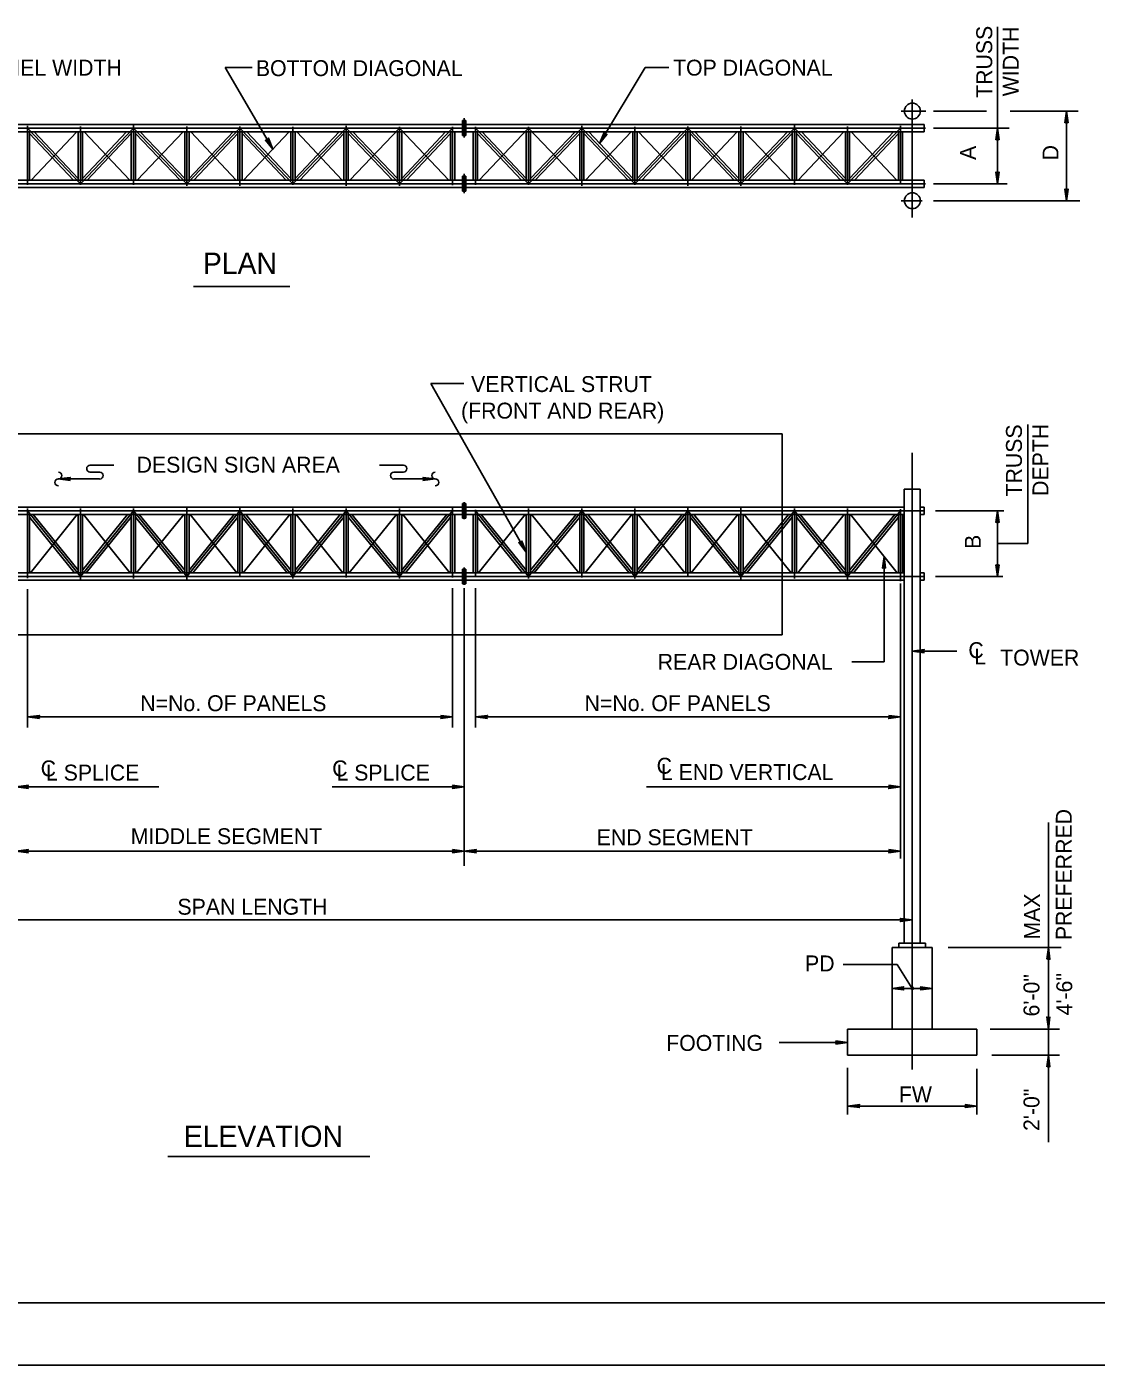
# Model space of a CAD drawing. Extents: x -3 to 26050223, y 0 to 12035012.
# Drawn here: x 14.2 to 31.01, y 0 to 21.04 of the extents above; entities that cross this region are included whole.
import ezdxf

# ---------------------------------------------------------------- set-up
doc = ezdxf.new("R2010")
doc.units = 0
for name, color, linetype in [('1', 7, 'Continuous'), ('2', 7, 'Continuous'), ('39', 7, 'Continuous')]:
    doc.layers.add(name, color=color, linetype=linetype)

msp = doc.modelspace()

# ---------------------------------------------------------------- linework, layer by layer
at = {"layer": '1'}
for p, q in [((29.458, 21.042), (29.458, 19.45)), ((17.317, 20.4), (18.067, 19.117)), ((17.317, 20.4), (17.742, 20.4)), ((23.2, 19.208), (23.917, 20.4)), ((23.917, 20.4), (24.292, 20.4)), ((28.117, 19.9), (28.117, 18.042)), ((21.075, 19.608), (21.075, 19.3)), ((21.075, 19.583), (21.075, 19.308)), ((27.942, 19.717), (28.333, 19.717)), ((28.45, 19.717), (29.283, 19.717)), ((29.658, 19.717), (30.725, 19.717)), ((30.542, 19.717), (30.542, 18.308)), ((6.792, 19.508), (28.308, 19.508)), ((6.792, 19.45), (28.325, 19.45)), ((6.792, 19.392), (28.308, 19.392)), ((14.208, 19.483), (14.208, 18.558)), ((15.042, 18.575), (14.208, 19.45)), ((14.242, 19.392), (14.242, 18.633)), ((14.242, 19.392), (14.242, 18.633)), ((14.933, 18.633), (14.242, 19.367)), ((14.983, 19.392), (14.267, 18.633)), ((15.008, 18.658), (14.317, 19.392)), ((15.008, 19.392), (15.008, 18.633)), ((15.042, 19.475), (15.042, 18.558)), ((15.875, 19.45), (15.042, 18.575)), ((15.767, 19.392), (15.075, 18.658)), ((15.075, 19.392), (15.075, 18.633)), ((15.817, 18.633), (15.1, 19.392)), ((15.842, 19.367), (15.15, 18.633)), ((15.842, 19.392), (15.842, 18.633)), ((15.875, 19.492), (15.875, 18.558)), ((16.717, 18.575), (15.875, 19.45)), ((15.908, 19.392), (15.908, 18.633)), ((16.608, 18.633), (15.908, 19.367)), ((16.658, 19.392), (15.933, 18.633)), ((16.683, 18.658), (15.983, 19.392)), ((16.683, 19.392), (16.683, 18.633)), ((16.717, 19.475), (16.717, 18.542)), ((17.55, 19.45), (16.717, 18.575)), ((17.442, 19.392), (16.75, 18.658)), ((16.75, 19.392), (16.75, 18.633)), ((17.492, 18.633), (16.775, 19.392)), ((17.517, 19.367), (16.825, 18.633)), ((17.517, 19.392), (17.517, 18.633)), ((17.55, 19.475), (17.55, 18.542)), ((18.383, 18.575), (17.55, 19.45)), ((17.583, 19.392), (17.583, 18.633)), ((18.275, 18.633), (17.583, 19.367)), ((18.325, 19.392), (17.608, 18.633)), ((18.35, 18.658), (17.658, 19.392)), ((18.35, 19.392), (18.35, 18.633)), ((18.383, 19.467), (18.383, 18.558)), ((19.217, 19.45), (18.383, 18.575)), ((19.108, 19.392), (18.417, 18.658)), ((18.417, 19.392), (18.417, 18.633)), ((19.158, 18.633), (18.442, 19.392)), ((19.183, 19.367), (18.492, 18.633)), ((19.183, 19.392), (19.183, 18.633)), ((19.217, 19.483), (19.217, 18.542)), ((20.058, 18.575), (19.217, 19.45)), ((19.25, 19.392), (19.25, 18.633)), ((19.95, 18.633), (19.25, 19.367)), ((20.058, 19.45), (19.275, 18.633)), ((20.025, 18.658), (19.325, 19.392)), ((20.025, 19.392), (20.025, 18.633)), ((20.058, 19.467), (20.058, 18.542)), ((20.892, 19.45), (20.058, 18.575)), ((20.833, 18.633), (20.058, 19.45)), ((20.783, 19.392), (20.092, 18.658)), ((20.092, 19.392), (20.092, 18.633)), ((20.858, 19.367), (20.167, 18.633)), ((20.858, 19.392), (20.858, 18.633)), ((20.892, 19.467), (20.892, 18.55)), ((20.925, 19.392), (20.925, 18.633)), ((21.05, 19.567), (21.05, 19.333)), ((21.05, 19.567), (21.1, 19.567)), ((21.1, 19.567), (21.1, 19.333)), ((21.217, 19.392), (21.217, 18.633)), ((21.25, 19.467), (21.25, 18.558)), ((21.25, 19.45), (22.083, 18.575)), ((21.283, 19.392), (21.283, 18.633)), ((21.283, 19.367), (21.975, 18.633)), ((21.308, 18.633), (22.083, 19.45)), ((21.358, 19.392), (22.05, 18.658)), ((22.05, 19.392), (22.05, 18.633)), ((22.083, 19.467), (22.083, 18.558)), ((22.083, 18.575), (22.925, 19.45)), ((22.083, 19.45), (22.867, 18.633)), ((22.117, 18.658), (22.817, 19.392)), ((22.117, 19.392), (22.117, 18.633)), ((22.192, 18.633), (22.892, 19.367)), ((22.892, 19.392), (22.892, 18.633)), ((22.925, 19.483), (22.925, 18.542)), ((22.925, 19.45), (23.758, 18.575)), ((22.958, 19.392), (22.958, 18.633)), ((22.958, 19.367), (23.65, 18.633)), ((22.983, 18.633), (23.7, 19.392)), ((23.033, 19.392), (23.725, 18.658)), ((23.725, 19.392), (23.725, 18.633)), ((23.758, 19.467), (23.758, 18.558)), ((23.758, 18.575), (24.592, 19.45)), ((23.792, 18.658), (24.483, 19.392)), ((23.792, 19.392), (23.792, 18.633)), ((23.817, 19.392), (24.533, 18.633)), ((23.867, 18.633), (24.558, 19.367)), ((24.558, 19.392), (24.558, 18.633)), ((24.592, 19.475), (24.592, 18.542)), ((24.592, 19.45), (25.425, 18.575)), ((24.625, 19.392), (24.625, 18.633)), ((24.625, 19.367), (25.317, 18.633)), ((24.65, 18.633), (25.367, 19.392)), ((24.7, 19.392), (25.392, 18.658)), ((25.392, 19.392), (25.392, 18.633)), ((25.425, 19.475), (25.425, 18.542)), ((25.425, 18.575), (26.267, 19.45)), ((25.458, 18.658), (26.158, 19.392)), ((25.458, 19.392), (25.458, 18.633)), ((25.483, 19.392), (26.208, 18.633)), ((25.533, 18.633), (26.233, 19.367)), ((26.233, 19.392), (26.233, 18.633)), ((26.267, 19.492), (26.267, 18.558)), ((26.267, 19.45), (27.1, 18.575)), ((26.3, 19.392), (26.3, 18.633)), ((26.3, 19.367), (26.992, 18.633)), ((26.325, 18.633), (27.042, 19.392)), ((26.375, 19.392), (27.067, 18.658)), ((27.067, 19.392), (27.067, 18.633)), ((27.1, 19.475), (27.1, 18.558)), ((27.1, 18.575), (27.933, 19.45)), ((27.133, 18.658), (27.825, 19.392)), ((27.133, 19.392), (27.133, 18.633)), ((27.158, 19.392), (27.875, 18.633)), ((27.208, 18.633), (27.9, 19.367)), ((27.9, 19.392), (27.9, 18.633)), ((27.933, 19.483), (27.933, 18.567)), ((27.967, 19.392), (27.967, 18.633)), ((28.308, 19.508), (28.308, 19.392)), ((28.45, 19.45), (29.642, 19.45)), ((29.458, 19.45), (29.458, 18.575)), ((21.05, 19.333), (21.1, 19.333)), ((21.075, 18.733), (21.075, 18.425)), ((6.792, 18.633), (28.308, 18.633)), ((6.792, 18.575), (28.325, 18.575)), ((21.05, 18.692), (21.05, 18.458)), ((21.05, 18.692), (21.1, 18.692)), ((21.075, 18.708), (21.075, 18.442)), ((21.1, 18.692), (21.1, 18.458)), ((28.308, 18.633), (28.308, 18.517)), ((28.45, 18.575), (29.608, 18.575)), ((6.792, 18.517), (28.308, 18.517)), ((21.05, 18.458), (21.1, 18.458)), ((27.942, 18.308), (28.275, 18.308)), ((28.45, 18.308), (30.75, 18.308)), ((20.55, 15.433), (21.067, 15.433)), ((22.05, 12.783), (20.55, 15.433)), ((29.933, 14.792), (29.933, 12.917)), ((9.108, 14.642), (26.075, 14.642)), ((26.075, 14.642), (26.075, 11.483)), ((28.117, 14.342), (28.117, 4.65)), ((15.192, 14.15), (15.567, 14.15)), ((20.117, 14.15), (19.742, 14.15)), ((14.692, 13.933), (15.342, 13.933)), ((15.192, 14.042), (15.342, 14.042)), ((20.117, 14.042), (19.967, 14.042)), ((20.617, 13.933), (19.967, 13.933)), ((27.992, 13.775), (28.242, 13.775)), ((27.992, 13.775), (27.992, 6.633)), ((28.242, 13.775), (28.242, 6.633)), ((7.108, 13.492), (27.992, 13.492)), ((16.717, 13.475), (16.717, 12.358)), ((17.55, 13.475), (17.55, 12.392)), ((20.892, 13.475), (20.892, 12.383)), ((21.05, 13.55), (21.05, 13.317)), ((21.05, 13.55), (21.1, 13.55)), ((21.075, 13.567), (21.075, 13.3)), ((21.1, 13.55), (21.1, 13.317)), ((24.592, 13.475), (24.592, 12.392)), ((25.425, 13.475), (25.425, 12.358)), ((28.242, 13.492), (28.308, 13.492)), ((28.242, 13.492), (28.308, 13.492)), ((28.308, 13.492), (28.308, 13.375)), ((6.675, 13.433), (28.308, 13.433)), ((7.108, 13.375), (27.992, 13.375)), ((14.208, 13.467), (14.208, 12.375)), ((15.042, 12.4), (14.208, 13.433)), ((14.242, 13.375), (14.242, 12.458)), ((14.95, 12.458), (14.242, 13.333)), ((14.992, 13.375), (14.258, 12.458)), ((15.008, 12.5), (14.3, 13.375)), ((15.008, 13.375), (15.008, 12.458)), ((15.042, 13.467), (15.042, 12.358)), ((15.875, 13.433), (15.042, 12.4)), ((15.075, 13.375), (15.075, 12.458)), ((15.783, 13.375), (15.075, 12.5)), ((15.825, 12.458), (15.092, 13.375)), ((15.842, 13.333), (15.133, 12.458)), ((15.842, 13.375), (15.842, 12.458)), ((15.875, 13.467), (15.875, 12.367)), ((16.717, 12.4), (15.875, 13.433)), ((15.908, 13.375), (15.908, 12.458)), ((16.625, 12.458), (15.908, 13.333)), ((16.667, 13.375), (15.925, 12.458)), ((16.683, 12.5), (15.967, 13.375)), ((16.683, 13.375), (16.683, 12.458)), ((17.55, 13.433), (16.717, 12.4)), ((16.75, 13.375), (16.75, 12.458)), ((17.458, 13.375), (16.75, 12.5)), ((17.5, 12.458), (16.767, 13.375)), ((17.517, 13.333), (16.808, 12.458)), ((17.517, 13.375), (17.517, 12.458)), ((18.383, 12.4), (17.55, 13.433)), ((17.583, 13.375), (17.583, 12.458)), ((18.292, 12.458), (17.583, 13.333)), ((18.333, 13.375), (17.6, 12.458)), ((18.35, 12.5), (17.642, 13.375)), ((18.35, 13.375), (18.35, 12.458)), ((18.383, 13.467), (18.383, 12.367)), ((19.217, 13.433), (18.383, 12.4)), ((18.417, 13.375), (18.417, 12.458)), ((19.125, 13.375), (18.417, 12.5)), ((19.167, 12.458), (18.433, 13.375)), ((19.183, 13.333), (18.475, 12.458)), ((19.183, 13.375), (19.183, 12.458)), ((19.217, 13.467), (19.217, 12.383)), ((20.058, 12.4), (19.217, 13.433)), ((19.25, 13.375), (19.25, 12.458)), ((19.967, 12.458), (19.25, 13.333)), ((20.008, 13.375), (19.267, 12.458)), ((20.025, 12.5), (19.308, 13.375)), ((20.025, 13.375), (20.025, 12.458)), ((20.058, 13.467), (20.058, 12.367)), ((20.892, 13.433), (20.058, 12.4)), ((20.092, 13.375), (20.092, 12.458)), ((20.8, 13.375), (20.092, 12.5)), ((20.842, 12.458), (20.108, 13.375)), ((20.858, 13.333), (20.15, 12.458)), ((20.858, 13.375), (20.858, 12.458)), ((20.925, 13.375), (20.925, 12.458)), ((21.05, 13.317), (21.1, 13.317)), ((21.217, 13.375), (21.217, 12.458)), ((21.25, 13.45), (21.25, 12.392)), ((21.25, 13.433), (22.083, 12.4)), ((21.283, 13.375), (21.283, 12.458)), ((21.283, 13.333), (21.992, 12.458)), ((21.3, 12.458), (22.033, 13.375)), ((21.342, 13.375), (22.05, 12.5)), ((22.05, 13.375), (22.05, 12.458)), ((22.083, 13.467), (22.083, 12.367)), ((22.083, 12.4), (22.925, 13.433)), ((22.117, 13.375), (22.117, 12.458)), ((22.117, 12.5), (22.833, 13.375)), ((22.133, 13.375), (22.875, 12.458)), ((22.175, 12.458), (22.892, 13.333)), ((22.892, 13.375), (22.892, 12.458)), ((22.925, 13.467), (22.925, 12.383)), ((22.925, 13.433), (23.758, 12.4)), ((22.958, 13.375), (22.958, 12.458)), ((22.958, 13.333), (23.667, 12.458)), ((22.975, 12.458), (23.708, 13.375)), ((23.017, 13.375), (23.725, 12.5)), ((23.725, 13.375), (23.725, 12.458)), ((23.758, 13.467), (23.758, 12.367)), ((23.758, 12.4), (24.592, 13.433)), ((23.792, 13.375), (23.792, 12.458)), ((23.792, 12.5), (24.5, 13.375)), ((23.808, 13.375), (24.542, 12.458)), ((23.85, 12.458), (24.558, 13.333)), ((24.558, 13.375), (24.558, 12.458)), ((24.592, 13.433), (25.425, 12.4)), ((24.625, 13.375), (24.625, 12.458)), ((24.625, 13.333), (25.333, 12.458)), ((24.642, 12.458), (25.375, 13.375)), ((24.683, 13.375), (25.392, 12.5)), ((25.392, 13.375), (25.392, 12.458)), ((25.425, 12.4), (26.267, 13.433)), ((25.458, 13.375), (25.458, 12.458)), ((25.458, 12.5), (26.175, 13.375)), ((25.475, 13.375), (26.217, 12.458)), ((25.517, 12.458), (26.233, 13.333)), ((26.233, 13.375), (26.233, 12.458)), ((26.267, 13.467), (26.267, 12.367)), ((26.267, 13.433), (27.1, 12.4)), ((26.3, 13.375), (26.3, 12.458)), ((26.3, 13.333), (27.008, 12.458)), ((26.317, 12.458), (27.05, 13.375)), ((26.358, 13.375), (27.067, 12.5)), ((27.067, 13.375), (27.067, 12.458)), ((27.1, 13.467), (27.1, 12.358)), ((27.1, 12.4), (27.933, 13.433)), ((27.133, 12.5), (27.842, 13.375)), ((27.133, 13.375), (27.133, 12.458)), ((27.15, 13.375), (27.883, 12.458)), ((27.192, 12.458), (27.9, 13.333)), ((27.9, 13.375), (27.9, 12.458)), ((27.933, 13.458), (27.933, 12.325)), ((27.967, 13.375), (27.967, 12.458)), ((28.242, 13.375), (28.308, 13.375)), ((28.242, 13.375), (28.308, 13.375)), ((28.483, 13.433), (29.558, 13.433)), ((29.458, 13.433), (29.458, 12.4)), ((29.933, 12.917), (29.458, 12.917)), ((27.675, 11.058), (27.675, 12.717)), ((7.108, 12.458), (27.992, 12.458)), ((21.05, 12.517), (21.05, 12.283)), ((21.05, 12.517), (21.1, 12.517)), ((21.075, 12.542), (21.075, 12.267)), ((21.1, 12.517), (21.1, 12.283)), ((28.242, 12.458), (28.308, 12.458)), ((28.308, 12.458), (28.308, 12.342)), ((6.7, 12.4), (28.3, 12.4)), ((7.108, 12.342), (27.992, 12.342)), ((20.892, 12.217), (20.892, 10.025)), ((21.05, 12.283), (21.1, 12.283)), ((21.075, 12.217), (21.075, 7.85)), ((21.25, 12.217), (21.25, 10.025)), ((28.242, 12.342), (28.308, 12.342)), ((28.483, 12.4), (29.542, 12.4)), ((14.208, 12.2), (14.208, 10.025)), ((9.108, 11.483), (26.075, 11.483)), ((28.117, 11.225), (28.817, 11.225)), ((27.167, 11.058), (27.675, 11.058)), ((14.208, 10.192), (20.892, 10.192)), ((21.25, 10.192), (27.933, 10.192)), ((14.033, 9.092), (16.275, 9.092)), ((19, 9.092), (21.075, 9.092)), ((23.942, 9.092), (27.933, 9.092)), ((30.258, 8.533), (30.258, 6.567)), ((6.983, 7), (28.117, 7)), ((27.8, 6.567), (28.433, 6.567)), ((27.8, 6.567), (27.8, 5.283)), ((27.908, 6.633), (27.908, 6.567)), ((27.908, 6.633), (28.325, 6.633)), ((28.325, 6.633), (28.325, 6.567)), ((28.433, 6.567), (28.433, 5.283)), ((28.683, 6.567), (30.458, 6.567)), ((30.258, 6.567), (30.258, 5.283)), ((27.033, 6.3), (27.883, 6.3)), ((27.883, 6.3), (28.117, 5.925)), ((27.8, 5.925), (28.433, 5.925)), ((27.1, 5.283), (27.1, 4.875)), ((27.1, 5.283), (29.133, 5.283)), ((29.133, 5.283), (29.133, 4.875)), ((29.342, 5.283), (30.433, 5.283)), ((30.258, 5.283), (30.258, 4.875)), ((26.025, 5.075), (27.1, 5.075)), ((27.1, 4.875), (29.133, 4.875)), ((29.367, 4.875), (30.433, 4.875)), ((30.258, 4.875), (30.258, 3.508)), ((27.1, 4.675), (27.1, 3.942)), ((29.133, 4.658), (29.133, 3.942)), ((27.1, 4.075), (29.133, 4.075)), ((3.6, 0.983), (68.183, 0.983)), ((68.892, 0), (0, 0))]:
    msp.add_line(p, q, dxfattribs=at)
for points in [[(30.542, 19.55), (30.517, 19.533), (30.542, 19.717), (30.567, 19.533)], [(23.283, 19.35), (23.317, 19.35), (23.2, 19.208), (23.275, 19.383)], [(29.458, 19.283), (29.433, 19.267), (29.458, 19.45), (29.483, 19.267)], [(17.983, 19.258), (18, 19.292), (18.067, 19.117), (17.95, 19.258)], [(29.458, 18.742), (29.483, 18.758), (29.458, 18.575), (29.433, 18.758)], [(30.542, 18.475), (30.567, 18.492), (30.542, 18.308), (30.517, 18.492)], [(14.883, 13.908), (14.692, 13.933), (14.883, 13.958), (14.858, 13.933)], [(20.425, 13.908), (20.617, 13.933), (20.425, 13.958), (20.45, 13.933)], [(21.967, 12.933), (21.983, 12.958), (22.05, 12.783), (21.933, 12.933)], [(28.308, 11.2), (28.117, 11.225), (28.308, 11.25), (28.283, 11.225)], [(14.4, 10.167), (14.208, 10.192), (14.4, 10.217), (14.375, 10.192)], [(20.708, 10.217), (20.892, 10.192), (20.708, 10.167), (20.725, 10.192)], [(21.442, 10.167), (21.25, 10.192), (21.442, 10.217), (21.417, 10.192)], [(27.75, 10.217), (27.933, 10.192), (27.75, 10.167), (27.767, 10.192)], [(14.225, 9.067), (14.033, 9.092), (14.225, 9.117), (14.2, 9.092)], [(20.892, 9.117), (21.075, 9.092), (20.892, 9.067), (20.908, 9.092)], [(27.75, 9.117), (27.933, 9.092), (27.75, 9.067), (27.767, 9.092)], [(14.225, 8.058), (14.033, 8.083), (14.225, 8.108), (14.2, 8.083)], [(20.892, 8.108), (21.075, 8.083), (20.892, 8.058), (20.908, 8.083)], [(21.267, 8.058), (21.075, 8.083), (21.267, 8.108), (21.242, 8.083)], [(27.75, 8.108), (27.933, 8.083), (27.75, 8.058), (27.767, 8.083)], [(30.233, 6.383), (30.258, 6.567), (30.283, 6.383), (30.258, 6.4)], [(27.967, 5.925), (27.983, 5.9), (27.8, 5.925), (27.983, 5.95)], [(28.267, 5.925), (28.25, 5.95), (28.433, 5.925), (28.25, 5.9)], [(30.283, 5.475), (30.258, 5.283), (30.233, 5.475), (30.258, 5.45)], [(26.933, 5.075), (26.917, 5.1), (27.1, 5.075), (26.917, 5.05)], [(30.233, 4.692), (30.258, 4.875), (30.283, 4.692), (30.258, 4.708)], [(27.292, 4.05), (27.1, 4.075), (27.292, 4.1), (27.267, 4.075)], [(28.95, 4.1), (29.133, 4.075), (28.95, 4.05), (28.967, 4.075)]]:
    msp.add_lwpolyline(points, close=True, dxfattribs=at)
for centre, radius in [((28.12, 19.717), 0.125), ((28.12, 18.308), 0.125), ((28.12, 5.925), 0.0167)]:
    msp.add_circle(centre, radius, dxfattribs=at)
for centre, start, end in [((15.195, 14.096), 90, 270), ((20.12, 14.096), 270, 90), ((14.695, 13.879), 90, 270), ((14.695, 13.987), 270, 90), ((15.345, 13.987), 270, 90), ((19.97, 13.987), 90, 270), ((20.62, 13.987), 90, 270), ((20.62, 13.879), 270, 90)]:
    msp.add_arc(centre, 0.0542, start, end, dxfattribs=at)
for points in [[(27.933, 12.292), (27.933, 7.967)], [(7.167, 8.083), (27.933, 8.083)]]:
    msp.add_open_spline(points, degree=1, dxfattribs=at)
at = {"layer": '2'}
for p, q in [((16.817, 16.958), (18.333, 16.958)), ((16.417, 3.283), (19.592, 3.283))]:
    msp.add_line(p, q, dxfattribs=at)
at = {"layer": '39'}
for points in [[(30.542, 19.55), (30.517, 19.533), (30.542, 19.717), (30.567, 19.533)], [(29.458, 13.267), (29.433, 13.25), (29.458, 13.433), (29.483, 13.25)], [(27.675, 12.55), (27.65, 12.533), (27.675, 12.717), (27.7, 12.533)], [(29.458, 12.567), (29.483, 12.583), (29.458, 12.4), (29.433, 12.583)], [(27.95, 7), (27.933, 7.025), (28.117, 7), (27.933, 6.975)], [(26.933, 5.075), (26.917, 5.1), (27.1, 5.075), (26.917, 5.05)]]:
    msp.add_lwpolyline(points, close=True, dxfattribs=at)

# ---------------------------------------------------------------- texts
at = {"layer": '1'}
for s, p in [('D', (30.417, 18.942)), ('PREFERRED', (30.625, 6.683)), ('MAX', (30.125, 6.692)), ('6\'-0"', (30.117, 5.483)), ('4\'-6"', (30.633, 5.5)), ('2\'-0"', (30.117, 3.683))]:
    msp.add_text(s, height=0.25, rotation=90, dxfattribs=at).set_placement(p)
for s, p in [('C', (29, 11.117)), ('L', (29.092, 11.017)), ('TOWER', (29.5, 11)), ('C', (24.1, 9.3)), ('L END VERTICAL ', (24.167, 9.2)), ('MIDDLE SEGMENT', (15.833, 8.192)), ('END SEGMENT', (23.158, 8.175)), ('FW', (27.908, 4.133))]:
    msp.add_text(s, height=0.25, dxfattribs=at).set_placement(p)
at = {"layer": '2'}
for s, p in [('TRUSS', (29.375, 19.925)), ('WIDTH', (29.792, 19.95)), ('A', (29.12, 18.949)), ('TRUSS', (29.842, 13.658)), ('DEPTH', (30.258, 13.667)), ('B', (29.195, 12.834))]:
    msp.add_text(s, height=0.25, rotation=90, dxfattribs=at).set_placement(p)
for s, height, p in [('PANEL WIDTH', 0.25, (13.408, 20.275)), ('BOTTOM DIAGONAL', 0.25, (17.8, 20.267)), ('TOP DIAGONAL', 0.25, (24.358, 20.275)), ('PLAN', 0.3334, (16.967, 17.158)), ('VERTICAL STRUT', 0.25, (21.183, 15.3)), ('(FRONT AND REAR)', 0.25, (21.025, 14.883)), ('DESIGN SIGN AREA', 0.25, (15.925, 14.033)), ('REAR DIAGONAL', 0.25, (24.117, 10.933)), ('N=No. OF PANELS', 0.25, (15.983, 10.283)), ('N=No. OF PANELS', 0.25, (22.967, 10.283)), ('C', 0.25, (14.417, 9.258)), ('C', 0.25, (19, 9.258)), ('L SPLICE', 0.25, (14.5, 9.192)), ('L SPLICE', 0.25, (19.067, 9.192)), ('SPAN LENGTH', 0.25, (16.567, 7.083)), ('PD', 0.25, (26.433, 6.192)), ('FOOTING', 0.25, (24.25, 4.942)), ('ELEVATION', 0.3334, (16.667, 3.433))]:
    msp.add_text(s, height=height, dxfattribs=at).set_placement(p)

doc.saveas('drawing.dxf')
